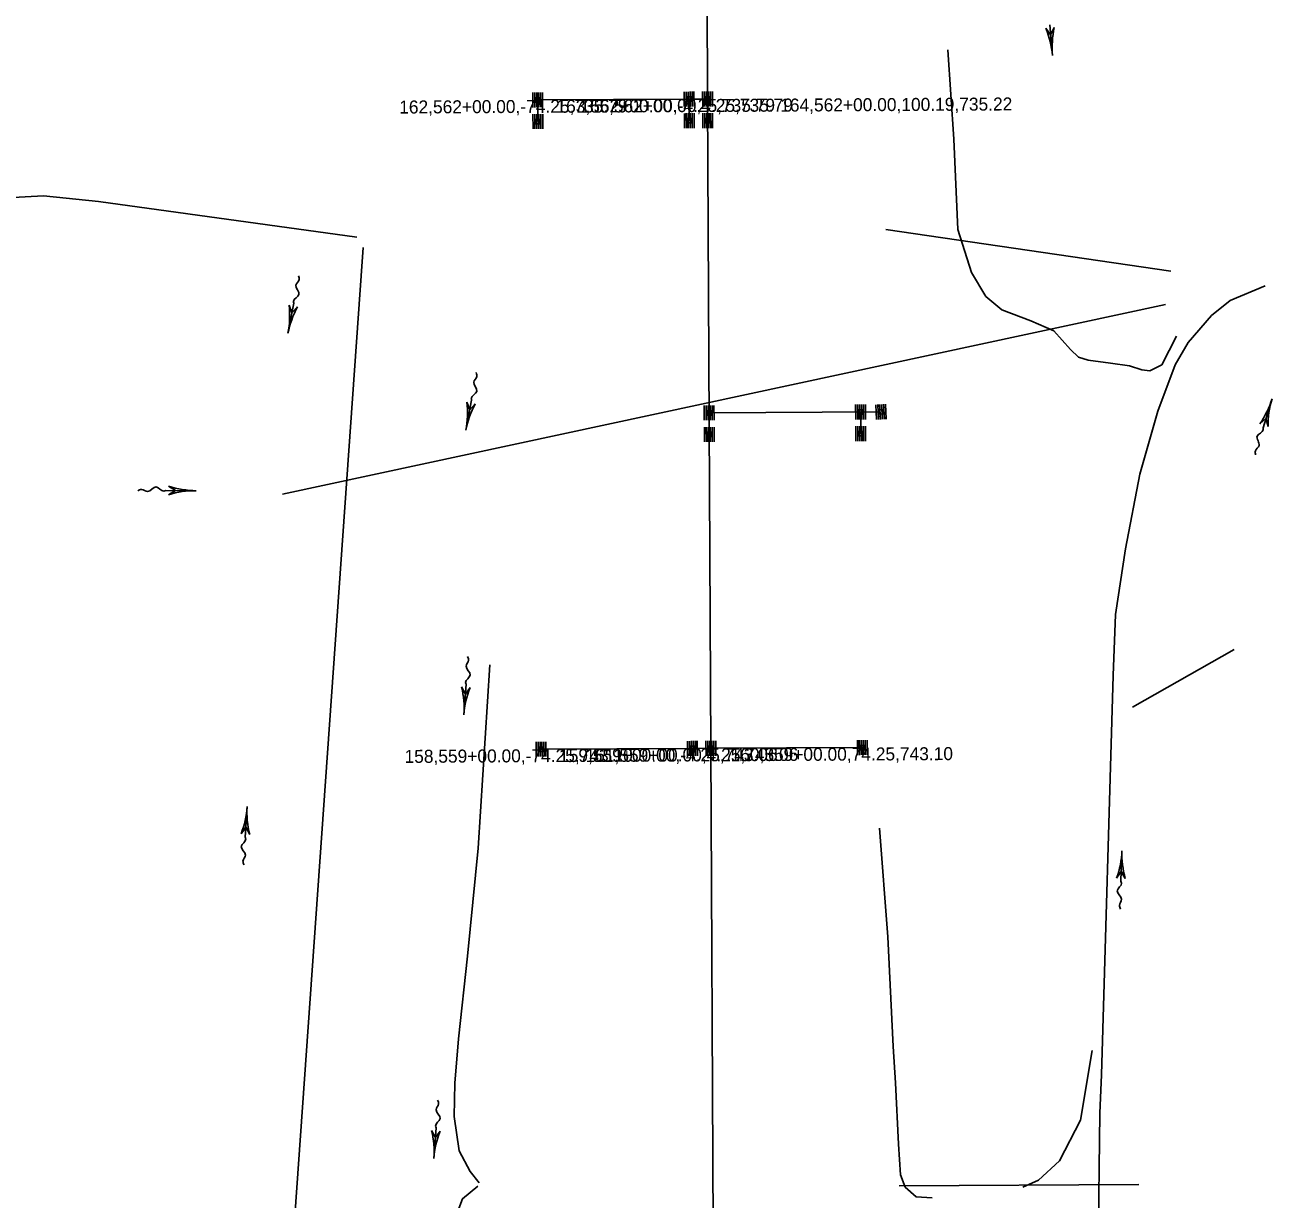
# Model space of a CAD drawing. Extents: x 593481 to 595859, y 150220 to 157407.
# Drawn here: x 594040 to 594616, y 154967 to 155509 of the extents above; entities that cross this region are included whole.
import ezdxf

# ---------------------------------------------------------------- set-up
doc = ezdxf.new("R2010")
doc.units = 0
for name, color, linetype in [('E_PROF_GridMin', 7, 'Continuous'), ('P_ALI_20_Tic', 7, 'Continuous'), ('P_ALI_50_Equation', 7, 'Continuous'), ('P_DRN_Pipes', 7, 'Continuous'), ('P_DRN_SS_UG', 7, 'Continuous')]:
    doc.layers.add(name, color=color, linetype=linetype)

msp = doc.modelspace()

# ---------------------------------------------------------------- linework, layer by layer
at = {"layer": 'E_PROF_GridMin'}
for p, q in [((594355.14, 155475.24), (594353.62, 155771.98)), ((594276.64, 155474.84), (594346.64, 155475.2)), ((594276.64, 155474.84), (594276.69, 155464.84)), ((594346.64, 155475.2), (594355.14, 155475.24)), ((594346.69, 155465.2), (594346.64, 155475.2)), ((594356.68, 155175.25), (594355.14, 155475.24)), ((594434.34, 155330.65), (594355.89, 155330.24)), ((594425.94, 155330.6), (594425.94, 155320.6)), ((594278.18, 155174.84), (594348.18, 155175.2)), ((594348.18, 155175.2), (594356.68, 155175.25)), ((594426.68, 155175.61), (594356.68, 155175.25)), ((594358.22, 154875.25), (594356.68, 155175.25))]:
    msp.add_line(p, q, dxfattribs=at)
for points in [[(594571.92, 155365.74), (594565.14, 155352.43), (594559.64, 155349.73), (594555.87, 155350.12), (594550.25, 155352.04), (594541.37, 155353.15), (594531.15, 155354.6), (594526.59, 155355.9), (594522.9, 155359.56), (594515.29, 155368.06), (594504.61, 155372.79), (594491.24, 155377.87), (594483.84, 155384), (594477.1, 155395.15), (594470.86, 155414.95), (594468.94, 155456.73), (594466.21, 155498.03)], [(594193.09, 155411.34), (594073.54, 155427.86), (594048.1, 155430.58), (594022.56, 155429.15), (594004.52, 155425.45), (593990.2, 155419.58), (593976.72, 155409.53), (593963.18, 155397.41), (593953.35, 155382.07), (593943.75, 155338.68), (593941.24, 155313.82), (593931.56, 155304.71), (593921.12, 155302.9), (593896.63, 155305.59), (593891.96, 155307.79), (593879.74, 155310.17), (593860.02, 155314.83), (593844.02, 155317.31), (593827.14, 155321.89), (593814.99, 155327.39)], [(594195.87, 155406.63), (594155.86, 154839.17), (594136.12, 154647.32), (594125.75, 154586.3), (594119.28, 154562.31), (594104.8, 154521.76), (594093.35, 154507.25), (594075.71, 154498.55), (594048.65, 154492.71), (593981.57, 154485.26), (593546.85, 154493.19), (593538.17, 154494.28), (593526.38, 154497.62), (593514.24, 154502.72), (593501.23, 154504.79), (593491.32, 154504.17), (593484.5, 154500.86), (593481.17, 154494.41)], [(594612.95, 155388.89), (594596.71, 155382.2), (594588.1, 155375.16), (594577.39, 155362.81), (594571.35, 155352.38), (594563.26, 155330.97), (594554.94, 155301.9), (594548.34, 155267.44), (594543.77, 155237.13), (594542.73, 155208.88), (594537.26, 155024.38), (594536.51, 155006.73), (594535.72, 154943.23), (594533.09, 154881.6), (594531.45, 154816.64), (594529.67, 154746.17)], [(594249.5, 154974.47), (594245.36, 154979.68), (594240.25, 154989.23), (594237.97, 155005.19), (594238.36, 155020.5), (594239.95, 155041.07), (594244.13, 155079.25), (594249.14, 155129.18), (594254.49, 155213.86)], [(594459.03, 154967.51), (594451.56, 154968.01), (594446.5, 154972.57), (594444.41, 154978.14), (594443.43, 154992.33), (594442.07, 155020.78), (594440.92, 155037.43), (594438.56, 155088.15), (594434.63, 155138.37)], [(594532.95, 155035.61), (594527.56, 155003.52), (594517.93, 154984.63), (594508.17, 154975.76), (594500.89, 154972.46)], [(594248.94, 154972.9), (594241.91, 154967.19), (594238.79, 154958.94), (594235.75, 154930.84), (594230.88, 154901.44), (594227.52, 154859.43), (594221.1, 154817.5), (594214.83, 154781.45), (594209.84, 154735.27), (594200.1, 154653.01), (594191.65, 154590.92), (594189.63, 154541.3), (594190.82, 154497.49), (594193.99, 154473.57)]]:
    msp.add_lwpolyline(points, dxfattribs=at)
at = {"layer": 'P_ALI_20_Tic'}
for p, q in [((594514.66, 155495.39), (594513.33, 155509.45)), ((594161.19, 155367.03), (594163.89, 155380.89)), ((594243.38, 155322.25), (594246.08, 155336.12)), ((594616.12, 155336.76), (594611.98, 155323.25)), ((594118.75, 155294.28), (594104.62, 155294.42)), ((594242.48, 155190.75), (594243.54, 155204.84)), ((594142.3, 155148.35), (594141.41, 155134.25)), ((594546.71, 155127.94), (594546.23, 155113.82)), ((594228.61, 154985.82), (594229.67, 154999.91))]:
    msp.add_line(p, q, dxfattribs=at)
for points in [[(594511.46, 155507.94), (594513.75, 155504.94), (594515.44, 155508.32)], [(594161.67, 155379.97), (594163.02, 155376.45), (594165.59, 155379.21)], [(594243.86, 155335.19), (594245.21, 155331.67), (594247.79, 155334.43)], [(594614.28, 155323.94), (594613.31, 155327.58), (594610.46, 155325.1)], [(594105.94, 155292.41), (594109.16, 155294.38), (594105.97, 155296.41)], [(594241.45, 155203.66), (594243.2, 155200.32), (594245.44, 155203.37)], [(594143.49, 155135.45), (594141.7, 155138.77), (594139.5, 155135.7)], [(594548.28, 155115.09), (594546.39, 155118.35), (594544.28, 155115.22)], [(594227.57, 154998.73), (594229.32, 154995.39), (594231.56, 154998.44)]]:
    msp.add_lwpolyline(points, dxfattribs=at)
for centre, start, end in [((594472.89, 155491.43), 5.41261, 23.17493), ((594556.43, 155499.34), 167.65029, 185.41261), ((594120, 155375.03), 349.00666, 6.76898), ((594202.38, 155359.02), 151.24434, 169.00666), ((594202.2, 155330.25), 349.00666, 6.76898), ((594576, 155349.05), 325.19326, 342.95558), ((594656.23, 155324.46), 162.95558, 180.7179), ((594284.57, 155314.25), 151.24434, 169.00666), ((594118.34, 155252.33), 89.4352, 107.19752), ((594119.17, 155336.24), 251.67288, 269.4352), ((594200.65, 155193.9), 355.6942, 13.45652), ((594284.32, 155187.6), 157.93188, 175.6942), ((594100.43, 155151), 338.61546, 356.37778), ((594184.17, 155145.7), 176.37778, 194.1401), ((594504.78, 155129.37), 340.28381, 358.04613), ((594588.65, 155126.51), 178.04613, 195.80845), ((594186.77, 154988.97), 355.6942, 13.45652), ((594270.44, 154982.67), 157.93188, 175.6942)]:
    msp.add_arc(centre, 41.96, start, end, dxfattribs=at)
for points in [[(594163.89, 155380.9), (594163.73, 155381.73), (594166.26, 155384.91), (594164.86, 155389.18), (594166.32, 155391.78), (594166.03, 155393.59)], [(594246.08, 155336.12), (594245.92, 155336.95), (594248.46, 155340.13), (594247.05, 155344.4), (594248.51, 155347), (594248.22, 155348.81)], [(594611.98, 155323.25), (594612.05, 155322.41), (594609.19, 155319.51), (594610.14, 155315.11), (594608.41, 155312.68), (594608.5, 155310.85)], [(594104.62, 155294.42), (594103.84, 155294.12), (594100.24, 155296.03), (594096.3, 155293.88), (594093.48, 155294.85), (594091.75, 155294.24)], [(594243.54, 155204.84), (594243.29, 155205.65), (594245.44, 155209.11), (594243.54, 155213.19), (594244.69, 155215.93), (594244.2, 155217.7)], [(594141.41, 155134.25), (594141.67, 155133.44), (594139.56, 155129.96), (594141.51, 155125.9), (594140.39, 155123.14), (594140.91, 155121.38)], [(594546.23, 155113.82), (594546.52, 155113.03), (594544.52, 155109.48), (594546.58, 155105.49), (594545.54, 155102.69), (594546.11, 155100.95)], [(594229.67, 154999.91), (594229.41, 155000.72), (594231.56, 155004.18), (594229.67, 155008.26), (594230.82, 155011), (594230.32, 155012.77)]]:
    msp.add_spline(points, degree=3, dxfattribs=at)
at = {"layer": 'P_DRN_Pipes'}
for p, q in [((594437.6, 155415.01), (594569.29, 155395.66)), ((594158.67, 155292.68), (594566.79, 155380.23)), ((594551.54, 155194.26), (594598.53, 155220.88)), ((594443.69, 154973.11), (594554.46, 154973.67))]:
    msp.add_line(p, q, dxfattribs=at)
at = {"layer": 'P_DRN_SS_UG'}
for p, q in [((594344.41, 155471.75), (594344.37, 155478.62)), ((594345.31, 155471.75), (594345.27, 155478.63)), ((594346.21, 155471.76), (594346.17, 155478.63)), ((594347.11, 155471.76), (594347.07, 155478.64)), ((594348.01, 155471.77), (594347.97, 155478.64)), ((594348.91, 155471.77), (594348.87, 155478.65)), ((594352.91, 155471.79), (594352.87, 155478.67)), ((594353.81, 155471.8), (594353.77, 155478.67)), ((594354.71, 155471.8), (594354.67, 155478.68)), ((594355.61, 155471.81), (594355.57, 155478.68)), ((594356.51, 155471.81), (594356.47, 155478.69)), ((594357.41, 155471.82), (594357.37, 155478.69)), ((594274.41, 155471.39), (594274.37, 155478.27)), ((594275.31, 155471.39), (594275.27, 155478.27)), ((594276.21, 155471.4), (594276.17, 155478.27)), ((594277.11, 155471.4), (594277.07, 155478.28)), ((594278.01, 155471.41), (594277.97, 155478.28)), ((594278.91, 155471.41), (594278.87, 155478.29)), ((594274.46, 155461.39), (594274.43, 155468.27)), ((594275.36, 155461.39), (594275.33, 155468.27)), ((594276.26, 155461.4), (594276.23, 155468.27)), ((594277.16, 155461.4), (594277.13, 155468.28)), ((594278.06, 155461.41), (594278.03, 155468.28)), ((594278.96, 155461.41), (594278.93, 155468.29)), ((594344.46, 155461.75), (594344.43, 155468.62)), ((594345.36, 155461.75), (594345.33, 155468.63)), ((594346.26, 155461.76), (594346.23, 155468.63)), ((594347.16, 155461.76), (594347.13, 155468.64)), ((594348.06, 155461.77), (594348.03, 155468.64)), ((594348.96, 155461.77), (594348.93, 155468.65)), ((594353.01, 155461.8), (594352.97, 155468.68)), ((594353.91, 155461.81), (594353.87, 155468.68)), ((594354.81, 155461.81), (594354.77, 155468.69)), ((594355.71, 155461.82), (594355.67, 155468.69)), ((594356.61, 155461.82), (594356.57, 155468.7)), ((594357.51, 155461.83), (594357.47, 155468.7)), ((594353.65, 155326.8), (594353.62, 155333.67)), ((594354.55, 155326.8), (594354.52, 155333.67)), ((594355.45, 155326.8), (594355.42, 155333.68)), ((594356.35, 155326.81), (594356.32, 155333.68)), ((594357.25, 155326.81), (594357.22, 155333.69)), ((594358.15, 155326.82), (594358.12, 155333.69)), ((594423.65, 155327.15), (594423.62, 155334.03)), ((594424.55, 155327.16), (594424.52, 155334.03)), ((594425.45, 155327.16), (594425.42, 155334.04)), ((594426.35, 155327.17), (594426.32, 155334.04)), ((594427.25, 155327.17), (594427.22, 155334.05)), ((594428.15, 155327.18), (594428.12, 155334.05)), ((594433.28, 155327.15), (594432.9, 155334.01)), ((594434.18, 155327.2), (594433.8, 155334.06)), ((594435.08, 155327.24), (594434.7, 155334.11)), ((594435.98, 155327.29), (594435.6, 155334.16)), ((594436.88, 155327.34), (594436.5, 155334.21)), ((594437.78, 155327.39), (594437.4, 155334.26)), ((594353.71, 155316.81), (594353.68, 155323.68)), ((594354.61, 155316.81), (594354.58, 155323.68)), ((594355.51, 155316.81), (594355.48, 155323.69)), ((594356.41, 155316.82), (594356.38, 155323.69)), ((594357.31, 155316.82), (594357.28, 155323.7)), ((594358.21, 155316.83), (594358.18, 155323.7)), ((594423.72, 155317.19), (594423.69, 155324.07)), ((594424.62, 155317.2), (594424.59, 155324.07)), ((594425.52, 155317.2), (594425.49, 155324.08)), ((594426.42, 155317.21), (594426.39, 155324.08)), ((594427.32, 155317.21), (594427.29, 155324.09)), ((594428.22, 155317.22), (594428.19, 155324.09)), ((594424.45, 155172.16), (594424.41, 155179.03)), ((594425.35, 155172.16), (594425.31, 155179.04)), ((594426.25, 155172.17), (594426.21, 155179.04)), ((594427.15, 155172.17), (594427.11, 155179.05)), ((594428.05, 155172.17), (594428.01, 155179.05)), ((594428.95, 155172.18), (594428.91, 155179.05)), ((594275.95, 155171.39), (594275.91, 155178.27)), ((594276.85, 155171.4), (594276.81, 155178.27)), ((594277.75, 155171.4), (594277.71, 155178.28)), ((594278.65, 155171.41), (594278.61, 155178.28)), ((594279.55, 155171.41), (594279.51, 155178.29)), ((594280.45, 155171.42), (594280.41, 155178.29)), ((594345.95, 155171.75), (594345.91, 155178.63)), ((594346.85, 155171.76), (594346.81, 155178.63)), ((594347.75, 155171.76), (594347.71, 155178.64)), ((594348.65, 155171.77), (594348.61, 155178.64)), ((594349.55, 155171.77), (594349.51, 155178.65)), ((594350.45, 155171.78), (594350.41, 155178.65)), ((594354.45, 155171.8), (594354.41, 155178.67)), ((594355.35, 155171.8), (594355.31, 155178.68)), ((594356.25, 155171.81), (594356.21, 155178.68)), ((594357.15, 155171.81), (594357.11, 155178.69)), ((594358.05, 155171.82), (594358.01, 155178.69)), ((594358.95, 155171.82), (594358.91, 155178.69))]:
    msp.add_line(p, q, dxfattribs=at)
for points in [[(594277.65, 155473.84), (594277.64, 155475.84), (594275.64, 155475.83), (594275.65, 155473.83)], [(594347.65, 155474.2), (594347.64, 155476.2), (594345.64, 155476.19), (594345.65, 155474.19)], [(594356.15, 155474.25), (594356.14, 155476.25), (594354.14, 155476.24), (594354.15, 155474.24)], [(594277.7, 155463.84), (594277.69, 155465.84), (594275.69, 155465.83), (594275.7, 155463.83)], [(594347.7, 155464.2), (594347.69, 155466.2), (594345.69, 155466.19), (594345.7, 155464.19)], [(594356.25, 155464.26), (594356.24, 155466.26), (594354.24, 155466.25), (594354.25, 155464.25)], [(594356.89, 155329.25), (594356.88, 155331.25), (594354.88, 155331.24), (594354.89, 155329.24)], [(594426.89, 155329.61), (594426.88, 155331.61), (594424.88, 155331.6), (594424.89, 155329.6)], [(594436.39, 155329.76), (594436.28, 155331.75), (594434.29, 155331.65), (594434.4, 155329.65)], [(594356.95, 155319.26), (594356.94, 155321.26), (594354.94, 155321.25), (594354.95, 155319.25)], [(594426.96, 155319.65), (594426.95, 155321.65), (594424.95, 155321.64), (594424.96, 155319.64)], [(594279.19, 155173.85), (594279.18, 155175.85), (594277.18, 155175.84), (594277.19, 155173.84)], [(594349.19, 155174.21), (594349.18, 155176.21), (594347.18, 155176.2), (594347.19, 155174.2)], [(594357.69, 155174.25), (594357.68, 155176.25), (594355.68, 155176.24), (594355.69, 155174.24)], [(594427.69, 155174.61), (594427.68, 155176.61), (594425.68, 155176.6), (594425.69, 155174.6)]]:
    msp.add_lwpolyline(points, close=True, dxfattribs=at)

# ---------------------------------------------------------------- texts
at = {"layer": 'P_ALI_50_Equation'}
for s, p in [('162,562+00.00,-74.25,735.79', (594212.62, 155468.51)), ('163,562+00.00,-4.25,735.79', (594285.31, 155468.88)), ('165,562+00.00,4.25,735.79', (594296.26, 155468.94)), ('164,562+00.00,100.19,735.22', (594388.75, 155469.41)), ('158,559+00.00,-74.25,743.10', (594215.08, 155168.52)), ('159,559+00.00,-4.25,743.06', (594286.52, 155168.89)), ('161,559+00.00,4.25,743.06', (594298.75, 155168.95)), ('160,559+00.00,74.25,743.10', (594365.79, 155169.29))]:
    msp.add_text(s, height=6, rotation=0.29409, dxfattribs=at).set_placement(p)

doc.saveas('drawing.dxf')
